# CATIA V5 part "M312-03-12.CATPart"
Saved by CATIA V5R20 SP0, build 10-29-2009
Part number: M312-03-12
Revision: TUTTO
Definition: NON CONOSCIUTO
Nomenclature: M312-03-12
Source: Unknown
Bounding box of the stored display mesh (mm): x -15 to 15, y -15 to 15, z -20.1 to 101.9
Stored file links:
  C:\Users\Utente\Desktop\IO LAVORO\3D X SITO CF\X SITO\M312-03\M312-03-12.CATPart
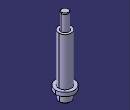
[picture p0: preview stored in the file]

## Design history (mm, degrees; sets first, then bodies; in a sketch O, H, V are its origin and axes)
Body1 "Sposta faccia1" (main body)
  Solid1: solid without history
